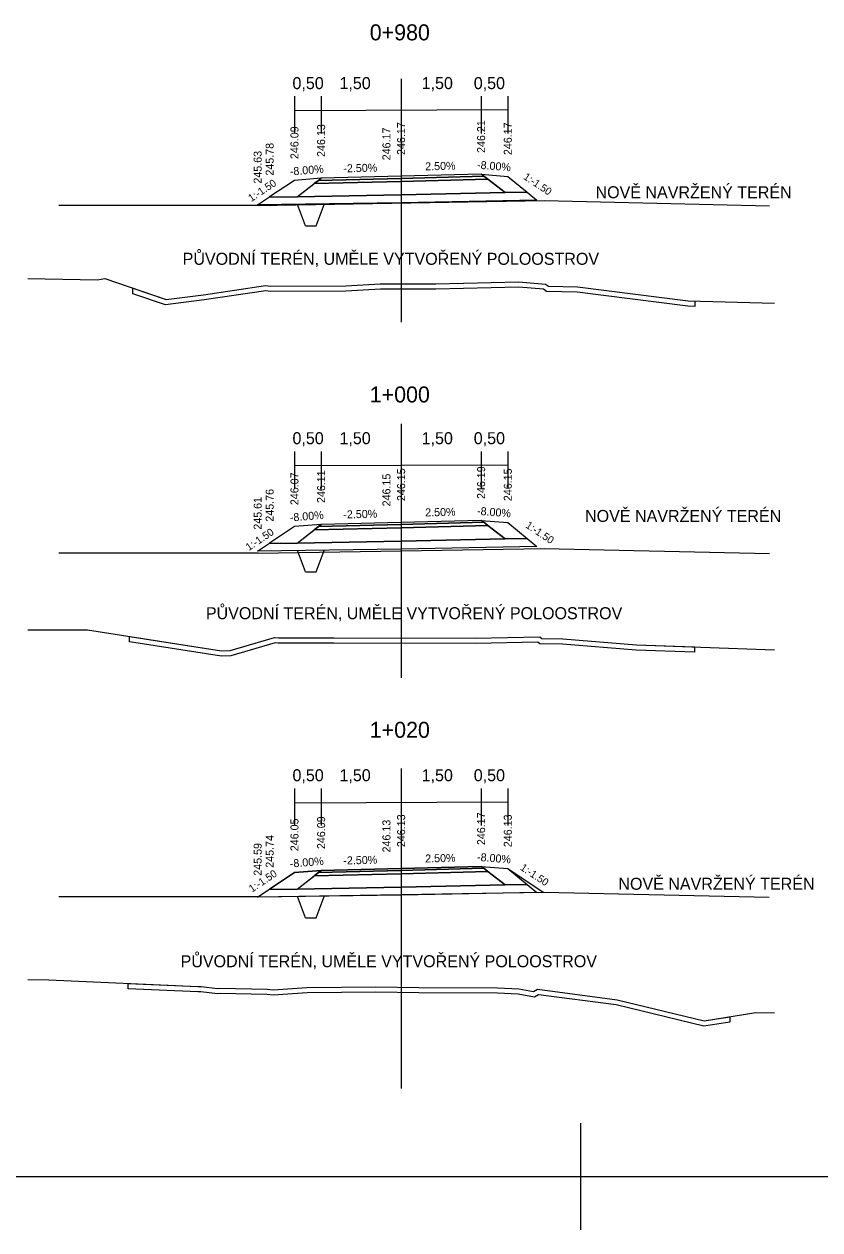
# Model space of a CAD drawing. Extents: x -552501 to -552394, y -1029983 to -1029892.
# Drawn here: x -552468.19 to -552453.26, y -1029983.45 to -1029960.84 of the extents above; entities that cross this region are included whole.
import ezdxf

# ---------------------------------------------------------------- set-up
doc = ezdxf.new("R2010")
doc.units = 0
for name, color, linetype in [('1', 7, 'Continuous'), ('16', 7, 'Continuous'), ('60', 7, 'Continuous'), ('9', 7, 'Continuous'), ('FORMATY', 7, 'Continuous'), ('Implicitní', 7, 'Continuous'), ('rámeček', 7, 'Continuous')]:
    doc.layers.add(name, color=color, linetype=linetype)

msp = doc.modelspace()

# ---------------------------------------------------------------- linework, layer by layer
for p, q in [((-552463.795, -1029964.243), (-552467.531, -1029964.243)), ((-552462.912, -1029964.625), (-552463.062, -1029964.225)), ((-552462.712, -1029964.625), (-552462.562, -1029964.225)), ((-552462.912, -1029964.625), (-552462.712, -1029964.625)), ((-552463.795, -1029970.763), (-552467.531, -1029970.763)), ((-552462.912, -1029971.113), (-552463.062, -1029970.713)), ((-552462.712, -1029971.113), (-552462.562, -1029970.713)), ((-552462.912, -1029971.113), (-552462.712, -1029971.113)), ((-552463.797, -1029977.208), (-552467.533, -1029977.208)), ((-552462.912, -1029977.601), (-552463.062, -1029977.201)), ((-552462.712, -1029977.601), (-552462.562, -1029977.201)), ((-552462.912, -1029977.601), (-552462.712, -1029977.601))]:
    msp.add_line(p, q)
for points in [[(-552462.616, -1029963.735), (-552463.116, -1029963.775), (-552463.581, -1029964.085), (-552463.066, -1029964.085)], [(-552463.066, -1029964.085), (-552462.744, -1029963.835), (-552461.116, -1029963.798), (-552459.488, -1029963.754), (-552459.166, -1029964.004), (-552461.116, -1029964.048)], [(-552461.116, -1029963.738), (-552462.667, -1029963.775), (-552462.744, -1029963.835), (-552461.116, -1029963.798), (-552459.488, -1029963.754), (-552459.565, -1029963.694), (-552461.116, -1029963.738), (-552459.565, -1029963.694), (-552459.616, -1029963.66), (-552461.116, -1029963.698), (-552462.616, -1029963.735), (-552462.667, -1029963.775)], [(-552462.744, -1029963.835), (-552462.667, -1029963.775), (-552461.116, -1029963.738), (-552459.565, -1029963.694), (-552459.488, -1029963.754), (-552461.116, -1029963.798)], [(-552459.616, -1029963.66), (-552459.116, -1029963.7), (-552458.755, -1029963.998), (-552459.166, -1029964.004), (-552459.488, -1029963.754), (-552459.565, -1029963.694)], [(-552463.806, -1029964.235), (-552463.581, -1029964.085), (-552463.066, -1029964.085), (-552461.116, -1029964.048), (-552459.166, -1029964.004), (-552458.755, -1029963.998), (-552458.57, -1029964.148), (-552461.116, -1029964.198)], [(-552466.146, -1029965.795), (-552465.524, -1029966.008), (-552464.82, -1029965.917), (-552463.659, -1029965.747), (-552463.561, -1029965.755), (-552462.154, -1029965.754), (-552461.507, -1029965.711), (-552460.465, -1029965.711), (-552458.908, -1029965.679), (-552458.407, -1029965.718), (-552458.355, -1029965.76), (-552457.809, -1029965.767), (-552455.734, -1029966.033), (-552455.612, -1029966.036), (-552455.612, -1029966.136), (-552455.742, -1029966.133), (-552457.816, -1029965.867), (-552458.391, -1029965.86), (-552458.446, -1029965.815), (-552458.911, -1029965.779), (-552460.464, -1029965.811), (-552461.504, -1029965.811), (-552462.151, -1029965.854), (-552463.565, -1029965.855), (-552463.655, -1029965.848), (-552464.807, -1029966.016), (-552465.534, -1029966.11), (-552466.146, -1029965.901)], [(-552462.616, -1029970.223), (-552463.116, -1029970.263), (-552463.581, -1029970.573), (-552463.066, -1029970.573)], [(-552463.066, -1029970.573), (-552462.744, -1029970.323), (-552461.116, -1029970.286), (-552459.488, -1029970.242), (-552459.166, -1029970.492), (-552461.116, -1029970.536)], [(-552461.116, -1029970.226), (-552462.667, -1029970.263), (-552462.744, -1029970.323), (-552461.116, -1029970.286), (-552459.488, -1029970.242), (-552459.565, -1029970.182), (-552461.116, -1029970.226), (-552459.565, -1029970.182), (-552459.616, -1029970.148), (-552461.116, -1029970.186), (-552462.616, -1029970.223), (-552462.667, -1029970.263)], [(-552462.744, -1029970.323), (-552462.667, -1029970.263), (-552461.116, -1029970.226), (-552459.565, -1029970.182), (-552459.488, -1029970.242), (-552461.116, -1029970.286)], [(-552459.616, -1029970.148), (-552459.116, -1029970.188), (-552458.755, -1029970.486), (-552459.166, -1029970.492), (-552459.488, -1029970.242), (-552459.565, -1029970.182)], [(-552463.806, -1029970.723), (-552463.581, -1029970.573), (-552463.066, -1029970.573), (-552461.116, -1029970.536), (-552459.166, -1029970.492), (-552458.755, -1029970.486), (-552458.57, -1029970.636), (-552461.116, -1029970.686)], [(-552466.206, -1029972.323), (-552464.481, -1029972.593), (-552464.324, -1029972.586), (-552463.488, -1029972.343), (-552463.416, -1029972.349), (-552462.379, -1029972.348), (-552459.725, -1029972.358), (-552458.517, -1029972.333), (-552458.48, -1029972.363), (-552458.083, -1029972.368), (-552456.702, -1029972.483), (-552455.616, -1029972.522), (-552455.616, -1029972.622), (-552456.708, -1029972.583), (-552458.088, -1029972.468), (-552458.516, -1029972.463), (-552458.552, -1029972.434), (-552459.724, -1029972.458), (-552462.379, -1029972.448), (-552463.42, -1029972.449), (-552463.478, -1029972.444), (-552464.308, -1029972.685), (-552464.487, -1029972.694), (-552466.206, -1029972.425)], [(-552461.116, -1029976.714), (-552462.667, -1029976.751), (-552462.744, -1029976.811), (-552461.116, -1029976.774), (-552459.488, -1029976.73), (-552459.565, -1029976.67), (-552461.116, -1029976.714), (-552459.565, -1029976.67), (-552459.616, -1029976.636), (-552461.116, -1029976.674), (-552462.616, -1029976.711), (-552462.667, -1029976.751)], [(-552462.744, -1029976.811), (-552462.667, -1029976.751), (-552461.116, -1029976.714), (-552459.565, -1029976.67), (-552459.488, -1029976.73), (-552461.116, -1029976.774)], [(-552459.616, -1029976.636), (-552459.116, -1029976.676), (-552458.755, -1029976.974), (-552459.166, -1029976.98), (-552459.488, -1029976.73), (-552459.565, -1029976.67)], [(-552462.616, -1029976.711), (-552463.116, -1029976.751), (-552463.581, -1029977.061), (-552463.066, -1029977.061)], [(-552463.066, -1029977.061), (-552462.744, -1029976.811), (-552461.116, -1029976.774), (-552459.488, -1029976.73), (-552459.166, -1029976.98), (-552461.116, -1029977.024)], [(-552463.806, -1029977.211), (-552463.581, -1029977.061), (-552463.066, -1029977.061), (-552461.116, -1029977.024), (-552459.166, -1029976.98), (-552458.755, -1029976.974), (-552458.57, -1029977.124), (-552461.116, -1029977.174)], [(-552466.231, -1029978.828), (-552464.925, -1029978.885), (-552464.868, -1029978.885), (-552464.559, -1029978.923), (-552464.514, -1029978.919), (-552463.625, -1029978.939), (-552463.514, -1029978.951), (-552462.883, -1029978.908), (-552461.59, -1029978.892), (-552460.781, -1029978.907), (-552459.306, -1029978.911), (-552458.911, -1029978.934), (-552458.634, -1029978.982), (-552458.562, -1029978.94), (-552457.063, -1029979.135), (-552455.434, -1029979.532), (-552454.951, -1029979.453), (-552454.951, -1029979.554), (-552455.438, -1029979.634), (-552457.082, -1029979.234), (-552458.541, -1029979.043), (-552458.615, -1029979.087), (-552458.922, -1029979.033), (-552459.309, -1029979.011), (-552460.782, -1029979.007), (-552461.591, -1029978.992), (-552462.879, -1029979.008), (-552463.516, -1029979.052), (-552463.632, -1029979.039), (-552464.511, -1029979.019), (-552464.561, -1029979.024), (-552464.874, -1029978.985), (-552464.927, -1029978.985), (-552466.231, -1029978.928)]]:
    msp.add_lwpolyline(points, close=True)
for points in [[(-552463.795, -1029964.243), (-552458.437, -1029964.153), (-552454.211, -1029964.25)], [(-552468.116, -1029965.612), (-552466.809, -1029965.638), (-552466.671, -1029965.616), (-552465.524, -1029966.008), (-552464.82, -1029965.917), (-552463.659, -1029965.747), (-552463.561, -1029965.755), (-552462.154, -1029965.754), (-552461.507, -1029965.711), (-552460.465, -1029965.711), (-552458.908, -1029965.679), (-552458.407, -1029965.718), (-552458.355, -1029965.76), (-552457.809, -1029965.767), (-552455.734, -1029966.033), (-552454.116, -1029966.075)], [(-552463.795, -1029970.763), (-552458.437, -1029970.673), (-552454.211, -1029970.77)], [(-552468.116, -1029972.2), (-552466.994, -1029972.2), (-552464.481, -1029972.593), (-552464.324, -1029972.586), (-552463.488, -1029972.343), (-552463.416, -1029972.349), (-552462.379, -1029972.348), (-552459.725, -1029972.358), (-552458.517, -1029972.333), (-552458.48, -1029972.363), (-552458.083, -1029972.368), (-552456.702, -1029972.483), (-552454.116, -1029972.575)], [(-552463.801, -1029977.208), (-552463.581, -1029977.061), (-552463.116, -1029976.751), (-552462.616, -1029976.711), (-552461.116, -1029976.674), (-552459.616, -1029976.636), (-552459.116, -1029976.676), (-552458.453, -1029977.118)], [(-552463.797, -1029977.208), (-552458.44, -1029977.118), (-552454.214, -1029977.215)], [(-552468.116, -1029978.756), (-552467.719, -1029978.764), (-552464.925, -1029978.885), (-552464.868, -1029978.885), (-552464.559, -1029978.923), (-552464.514, -1029978.919), (-552463.625, -1029978.939), (-552463.514, -1029978.951), (-552462.883, -1029978.908), (-552461.59, -1029978.892), (-552460.781, -1029978.907), (-552459.306, -1029978.911), (-552458.911, -1029978.934), (-552458.634, -1029978.982), (-552458.562, -1029978.94), (-552457.063, -1029979.135), (-552455.434, -1029979.532), (-552454.467, -1029979.373), (-552454.116, -1029979.38)]]:
    msp.add_lwpolyline(points)
at = {"layer": '60'}
for p, q in [((-552461.116, -1029961.869), (-552461.116, -1029966.432)), ((-552461.116, -1029968.336), (-552461.116, -1029973.1)), ((-552461.116, -1029974.802), (-552461.116, -1029980.802))]:
    msp.add_line(p, q, dxfattribs=at)
at = {"layer": '9'}
for p, q in [((-552463.116, -1029962.198), (-552463.116, -1029962.896)), ((-552462.616, -1029962.198), (-552462.616, -1029962.896)), ((-552461.116, -1029962.198), (-552461.116, -1029963.698)), ((-552459.616, -1029962.198), (-552459.616, -1029962.896)), ((-552459.116, -1029962.198), (-552459.116, -1029962.896)), ((-552463.116, -1029968.855), (-552463.116, -1029969.552)), ((-552462.616, -1029968.855), (-552462.616, -1029969.552)), ((-552461.116, -1029968.855), (-552461.116, -1029970.355)), ((-552459.616, -1029968.855), (-552459.616, -1029969.552)), ((-552459.116, -1029968.855), (-552459.116, -1029969.552)), ((-552463.116, -1029975.174), (-552463.116, -1029975.871)), ((-552462.616, -1029975.174), (-552462.616, -1029975.871)), ((-552461.116, -1029975.174), (-552461.116, -1029976.674)), ((-552459.616, -1029975.174), (-552459.616, -1029975.871)), ((-552459.116, -1029975.174), (-552459.116, -1029975.871))]:
    msp.add_line(p, q, dxfattribs=at)
at = {"layer": 'FORMATY'}
for p, q in [((-552457.755, -1029981.45), (-552457.755, -1029983.45)), ((-552458.755, -1029982.45), (-552456.755, -1029982.45))]:
    msp.add_line(p, q, dxfattribs=at)
at = {"layer": 'Implicitní'}
for p, q in [((-552463.106, -1029962.465), (-552459.116, -1029962.448)), ((-552463.106, -1029969.122), (-552459.116, -1029969.105)), ((-552463.106, -1029975.441), (-552459.116, -1029975.424))]:
    msp.add_line(p, q, dxfattribs=at)
at = {"layer": 'rámeček'}
for p, q in [((-552457.755, -1029981.95), (-552457.755, -1029982.45)), ((-552499.755, -1029982.45), (-552436.755, -1029982.45)), ((-552499.755, -1029982.45), (-552415.755, -1029982.45)), ((-552499.755, -1029982.45), (-552415.755, -1029982.45))]:
    msp.add_line(p, q, dxfattribs=at)

# ---------------------------------------------------------------- texts
for rotation, p in [(33.6902, (-552463.926, -1029964.182)), (326.3098, (-552458.836, -1029963.739)), (33.6902, (-552463.972, -1029970.725)), (326.3098, (-552458.795, -1029970.274)), (326.3098, (-552458.895, -1029976.689)), (33.6902, (-552463.913, -1029977.128))]:
    msp.add_text('1:-1.50', height=0.14, rotation=rotation).set_placement(p)
at = {"layer": '1'}
for s, p in [('0+980', (-552461.704, -1029961.149)), ('1+000', (-552461.704, -1029967.937)), ('1+020', (-552461.704, -1029974.225))]:
    msp.add_text(s, height=0.3, dxfattribs=at).set_placement(p)
at = {"layer": '16'}
for s, p in [('0,50', (-552463.153, -1029962.063)), ('1,50', (-552462.272, -1029962.063)), ('1,50', (-552460.731, -1029962.063)), ('0,50', (-552459.754, -1029962.063)), ('NOVĚ NAVRŽENÝ TERÉN', (-552457.471, -1029964.109)), ('PŮVODNÍ TERÉN, UMĚLE VYTVOŘENÝ POLOOSTROV', (-552465.212, -1029965.357)), ('0,50', (-552463.153, -1029968.72)), ('1,50', (-552462.272, -1029968.72)), ('1,50', (-552460.731, -1029968.72)), ('0,50', (-552459.754, -1029968.72)), ('NOVĚ NAVRŽENÝ TERÉN', (-552457.667, -1029970.178)), ('PŮVODNÍ TERÉN, UMĚLE VYTVOŘENÝ POLOOSTROV', (-552464.777, -1029972.001)), ('0,50', (-552463.153, -1029975.039)), ('1,50', (-552462.272, -1029975.039)), ('1,50', (-552460.731, -1029975.039)), ('0,50', (-552459.754, -1029975.039)), ('NOVĚ NAVRŽENÝ TERÉN', (-552457.042, -1029977.074)), ('PŮVODNÍ TERÉN, UMĚLE VYTVOŘENÝ POLOOSTROV', (-552465.251, -1029978.526))]:
    msp.add_text(s, height=0.225, dxfattribs=at).set_placement(p)
for s, rotation, p in [('246.21', 90, (-552459.541, -1029963.26)), ('246.09', 90, (-552463.041, -1029963.375)), ('246.13', 90, (-552462.541, -1029963.335)), ('246.17', 90, (-552461.316, -1029963.398)), ('246.17', 90, (-552461.041, -1029963.298)), ('246.17', 90, (-552459.041, -1029963.3)), ('245.78', 90, (-552463.506, -1029963.685)), ('245.63', 90, (-552463.731, -1029963.835)), ('-8.00%', 4.5739, (-552463.197, -1029963.682)), ('-2.50%', 1.4321, (-552462.198, -1029963.625)), ('2.50%', 1.4321, (-552460.663, -1029963.587)), ('-8.00%', 355.4261, (-552459.697, -1029963.554)), ('246.15', 90, (-552461.041, -1029969.786)), ('246.19', 90, (-552459.541, -1029969.748)), ('246.15', 90, (-552459.041, -1029969.788)), ('246.07', 90, (-552463.041, -1029969.863)), ('246.11', 90, (-552462.541, -1029969.823)), ('246.15', 90, (-552461.316, -1029969.886)), ('245.76', 90, (-552463.506, -1029970.173)), ('245.61', 90, (-552463.731, -1029970.323)), ('-8.00%', 4.5739, (-552463.197, -1029970.17)), ('-2.50%', 1.4321, (-552462.198, -1029970.113)), ('2.50%', 1.4321, (-552460.663, -1029970.075)), ('-8.00%', 355.4261, (-552459.697, -1029970.042)), ('246.05', 90, (-552463.041, -1029976.351)), ('246.09', 90, (-552462.541, -1029976.311)), ('246.13', 90, (-552461.316, -1029976.374)), ('246.13', 90, (-552461.041, -1029976.274)), ('246.17', 90, (-552459.541, -1029976.236)), ('246.13', 90, (-552459.041, -1029976.276)), ('245.59', 90, (-552463.731, -1029976.811)), ('245.74', 90, (-552463.506, -1029976.661)), ('-2.50%', 1.4321, (-552462.198, -1029976.601)), ('2.50%', 1.4321, (-552460.663, -1029976.563)), ('-8.00%', 355.4261, (-552459.697, -1029976.53)), ('-8.00%', 4.5739, (-552463.197, -1029976.658))]:
    msp.add_text(s, height=0.15, rotation=rotation, dxfattribs=at).set_placement(p)

doc.saveas('drawing.dxf')
